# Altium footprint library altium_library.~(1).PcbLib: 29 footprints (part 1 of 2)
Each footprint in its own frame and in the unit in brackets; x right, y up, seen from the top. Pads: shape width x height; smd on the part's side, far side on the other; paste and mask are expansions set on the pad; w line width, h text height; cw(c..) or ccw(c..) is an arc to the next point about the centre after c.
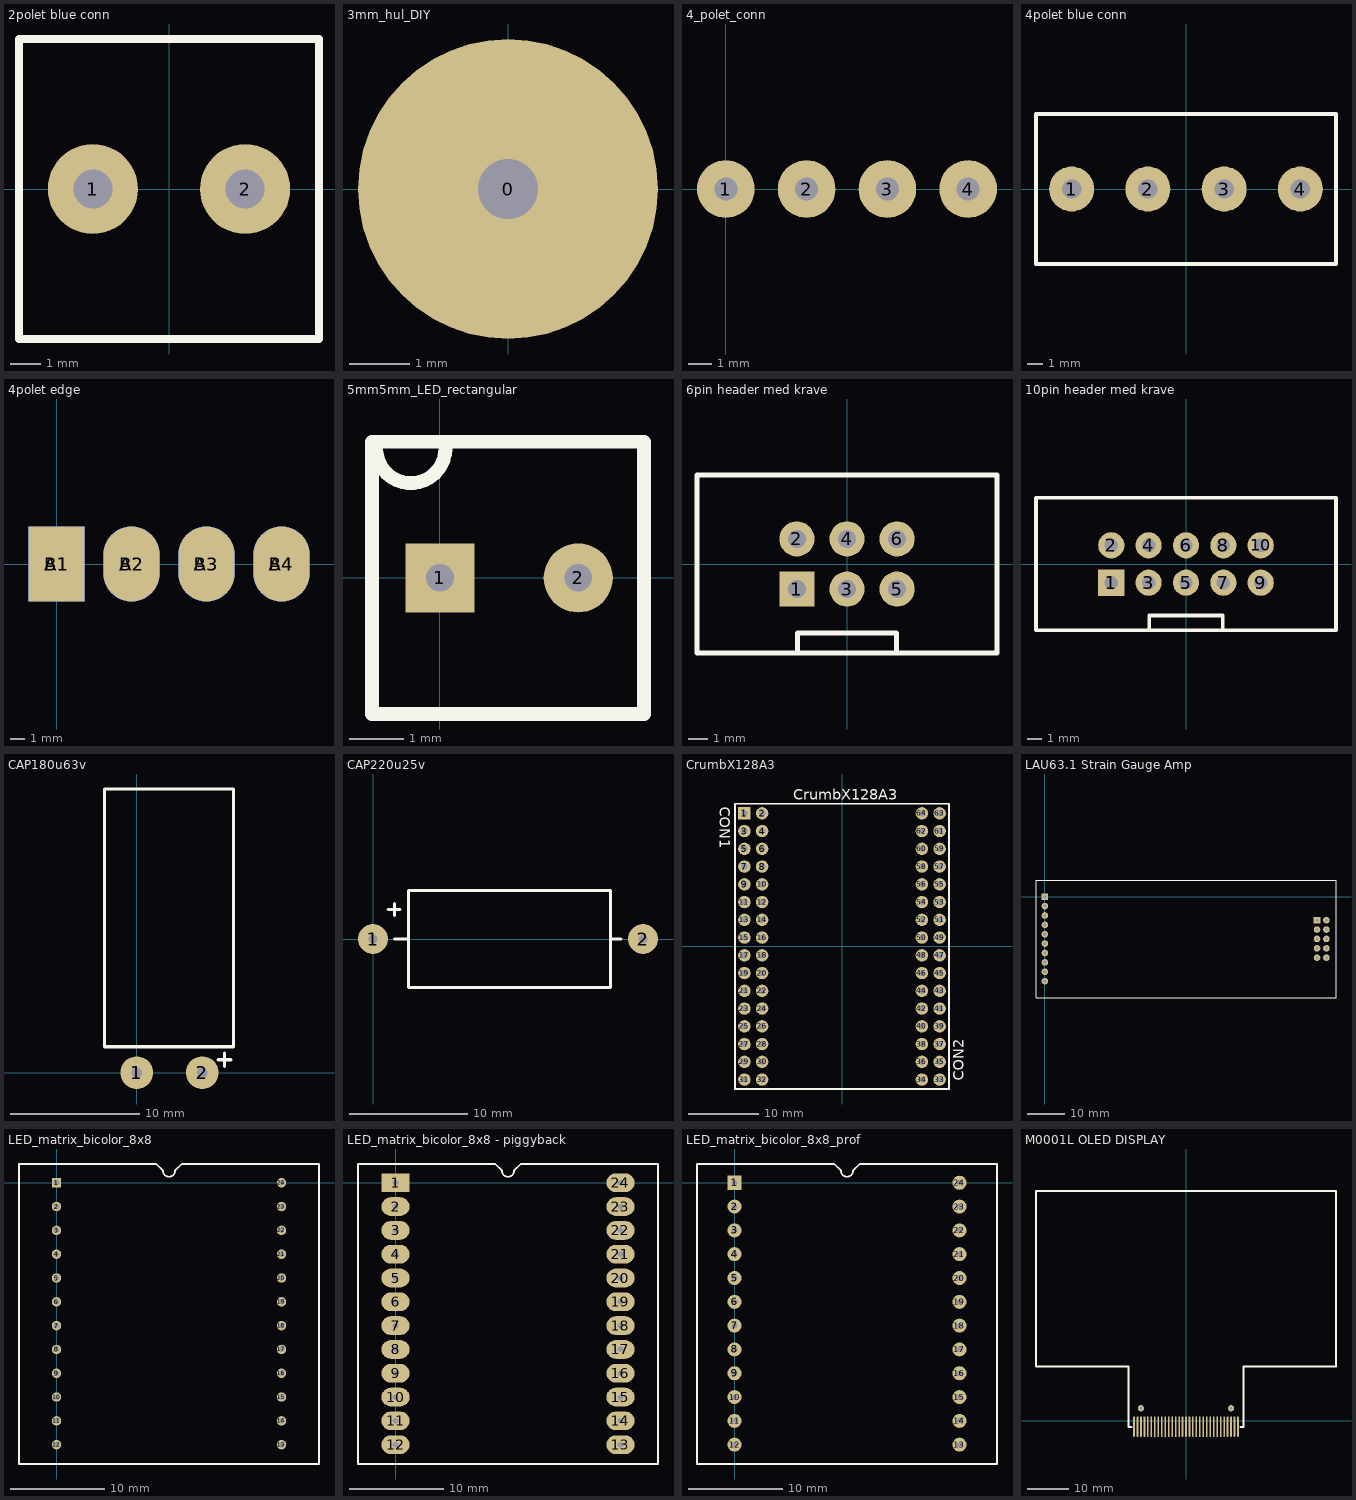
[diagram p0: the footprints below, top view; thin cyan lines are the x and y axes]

## 2polet blue conn [mm]
pads (2):
  round 3 hole 1.3: 1(-2.54,0) 2(2.54,0)
Top Overlay:
  lines w0.254: -5,-5 -5,5 5,5 5,-5 -5,-5

## 3mm_hul_DIY [mm]
pads (1):
  round 5 hole 1: 0(0,0)

## 4_polet_conn [mm]
pads (4):
  round 2.5 hole 1: 1(0,0) 2(3.5,0) 3(7,0) 4(10.5,0)

## 4polet blue conn [mm]
pads (4):
  round 3 hole 1.3: 1(-7.62,0) 2(-2.54,0) 3(2.54,0) 4(7.62,0)
Top Overlay:
  lines w0.254: -10,-5 -10,5 10,5 10,-5 -10,-5

## 4polet edge [mil]
pads (8):
  rect 150x200 smd: A1(0,0)
  oval 150x200 smd: A2(200,0) A3(400,0) A4(600,0)
  rect 150x200 smd far side: B1(0,0)
  oval 150x200 smd far side: B2(200,0) B3(400,0) B4(600,0)

## 5mm5mm_LED_rectangular [mil]
pads (2):
  rect 50x50 hole 20: 1(0,0)
  round 50 hole 20: 2(100,0)
Top Overlay:
  lines w10: -46.06,93.5 ccw(c-21.06,93.5) 3.94,93.5 ; 25,98.43 147.64,98.43 147.64,-98.43 -49.21,-98.43 -49.21,98.43 75,98.43

## 6pin header med krave [mil]
pads (6):
  rect 70x70 hole 35.43: 1(-100,-50)
  round 70 hole 35.43: 2(-100,50) 3(0,-50) 4(0,50) 5(100,-50) 6(100,50)
Top Overlay:
  lines w10: -98.43,-173.23 -98.43,-137.8 98.43,-137.8 98.43,-173.23 ; -299.21,-177.17 299.21,-177.17 299.21,177.17 -299.21,177.17 -299.21,-177.17

## 10pin header med krave [mil]
pads (10):
  rect 70x70 hole 35.43: 1(-200,-50)
  round 70 hole 35.43: 2(-200,50) 3(-100,-50) 4(-100,50) 5(0,-50) 6(0,50) 7(100,-50) 8(100,50) 9(200,-50) 10(200,50)
Top Overlay:
  lines w10: -98.43,-173.23 -98.43,-137.8 98.43,-137.8 98.43,-173.23 ; -401.57,-177.17 401.57,-177.17 401.57,177.17 -401.57,177.17 -401.57,-177.17

## CAP180u63v [mm]
pads (2):
  round 2.54 hole 0.8: 1(0,0) 2(5.08,0)
Top Overlay:
  lines w0.254: 6.3,1 7.316,1 ; 6.81,0.492 6.81,1.508 ; -2.5,2 -2.5,22 7.5,22 7.5,2 -2.5,2

## CAP220u25v [mm]
pads (2):
  round 2.54 hole 0.8: 1(0,0) 2(22.86,0)
Top Overlay:
  lines w0.254: 1.284,2.5 2.3,2.5 ; 1.8,0 3,0 3,4.1 20.1,4.1 20.1,-4.1 3,-4.1 3,-1.045 3,0.3 ; 1.8,2 1.8,3.016 ; 20.1,0 21,0

## CrumbX128A3 [mil]
pads (64):
  rect 70x70 hole 35.43: 1(-550,750)
  round 70 hole 35.43: 2(-450,750) 3(-550,650) 4(-450,650) 5(-550,550) 6(-450,550) 7(-550,450) 8(-450,450) 9(-550,350) 10(-450,350) 11(-550,250) 12(-450,250) 13(-550,150) 14(-450,150) 15(-550,50) 16(-450,50) 17(-550,-50.12) 18(-450,-50.12) 19(-550,-150) 20(-450,-150) 21(-550,-250) 22(-450,-250) 23(-550,-350) 24(-450,-350) 25(-550,-450) 26(-450,-450) 27(-550,-550) 28(-450,-550) 29(-550,-650) 30(-450,-650) 31(-550,-750) 32(-450,-750) 33(550,-750) 34(450,-750) 35(550,-650) 36(450,-650) 37(550,-550) 38(450,-550) 39(550,-450) 40(450,-450) 41(550,-350) 42(450,-350) 43(550,-250) 44(450,-250) 45(550,-150) 46(450,-150) 47(550,-50.12) 48(450,-50.12) 49(550,50) 50(450,50) 51(550,150) 52(450,150) 53(550,250) 54(450,250) 55(550,350) 56(450,350) 57(550,450) 58(450,450) 59(550,550) 60(450,550) 61(550,650) 62(450,650) 63(550,750) 64(450,750)
Top Overlay:
  lines w10: -602.36,-803.15 602.36,-803.15 602.36,803.15 -602.36,803.15 -602.36,-803.15
  text "CrumbX128A3" at -275.59,826.77 h60
  text "." at 633.86,-787.4 h60
  text "CON2" at 685.04,-755.91 h60
  text "CON1" at -688.98,787.4 h60

## LAU63.1 Strain Gauge Amp [mil]
pads (20):
  rect 70x70 hole 35: 0(0,0) 10(2900,-250)
  round 70 hole 35: 1(0,-100) 2(0,-200) 3(0,-300) 4(0,-400) 5(0,-500) 6(0,-600) 7(0,-700) 8(0,-800) 9(0,-900) 11(3000,-250) 12(2900,-350) 13(3000,-350) 14(2900,-450) 15(3000,-450) 16(2900,-550) 17(3000,-550) 18(2900,-650) 19(3000,-650)
Top Overlay:
  lines w10: -94.49,-1078.74 3102.36,-1078.74 3102.36,177.17 1345.28,177.17 -94.49,177.17 -94.49,-1078.74

## LED_matrix_bicolor_8x8 [mm]
pads (24):
  rect 1x1 / inner rect 3x2 / far side rect 3x2 hole 0.6: 1(0,0)
  round 1 / inner oval 3x2 / far side oval 3x2 hole 0.6: 2(0,-2.54) 3(0,-5.08) 4(0,-7.62) 5(0,-10.16) 6(0,-12.7) 7(0,-15.24) 8(0,-17.78) 9(0,-20.32) 10(0,-22.86) 11(0,-25.4) 12(0,-27.94) 13(24,-27.94) 14(24,-25.4) 15(24,-22.86) 16(24,-20.32) 17(24,-17.78) 18(24,-15.24) 19(24,-12.7) 20(24,-10.16) 21(24,-7.62) 22(24,-5.08) 23(24,-2.54) 24(24,0)
Top Overlay:
  lines w0.2: -4,-30 28,-30 28,2 13.365,2 12.635,1.27 cw(c12,1.27) 11.365,1.27 10.635,2 -4,2 -4,-30

## LED_matrix_bicolor_8x8 - piggyback [mm]
pads (24):
  rect 3x2 hole 0.6: 1(0,0)
  oval 3x2 hole 0.6: 2(0,-2.54) 3(0,-5.08) 4(0,-7.62) 5(0,-10.16) 6(0,-12.7) 7(0,-15.24) 8(0,-17.78) 9(0,-20.32) 10(0,-22.86) 11(0,-25.4) 12(0,-27.94) 13(24,-27.94) 14(24,-25.4) 15(24,-22.86) 16(24,-20.32) 17(24,-17.78) 18(24,-15.24) 19(24,-12.7) 20(24,-10.16) 21(24,-7.62) 22(24,-5.08) 23(24,-2.54) 24(24,0)
Top Overlay:
  lines w0.2: -4,-30 28,-30 28,2 13.365,2 12.635,1.27 cw(c12,1.27) 11.365,1.27 10.635,2 -4,2 -4,-30

## LED_matrix_bicolor_8x8_prof [mm] "made for proffesional pcb manuf."
height 8
pads (24):
  rect 1.5x1.5 hole 0.6: 1(0,0)
  round 1.5 hole 0.6: 2(0,-2.54) 3(0,-5.08) 4(0,-7.62) 5(0,-10.16) 6(0,-12.7) 7(0,-15.24) 8(0,-17.78) 9(0,-20.32) 10(0,-22.86) 11(0,-25.4) 12(0,-27.94) 13(24,-27.94) 14(24,-25.4) 15(24,-22.86) 16(24,-20.32) 17(24,-17.78) 18(24,-15.24) 19(24,-12.7) 20(24,-10.16) 21(24,-7.62) 22(24,-5.08) 23(24,-2.54) 24(24,0)
Top Overlay:
  lines w0.2: -4,-30 28,-30 28,2 13.365,2 12.635,1.27 cw(c12,1.27) 11.365,1.27 10.635,2 -4,2 -4,-30

## M0001L OLED DISPLAY [mm]
pads (33):
  oval 0.4x5 smd: 1(-12.675,-1.5) 2(-11.83,-1.5) 3(-10.985,-1.5) 4(-10.14,-1.5) 5(-9.295,-1.5) 6(-8.45,-1.5) 7(-7.605,-1.5) 8(-6.76,-1.5) 9(-5.915,-1.5) 10(-5.07,-1.5) 11(-4.225,-1.5) 12(-3.38,-1.5) 13(-2.535,-1.5) 14(-1.69,-1.5) 15(-0.845,-1.5) 16(0,-1.5) 17(0.845,-1.5) 18(1.69,-1.5) 19(2.535,-1.5) 20(3.38,-1.5) 21(4.225,-1.5) 22(5.07,-1.5) 23(5.915,-1.5) 24(6.76,-1.5) 25(7.605,-1.5) 26(8.45,-1.5) 27(9.295,-1.5) 28(10.14,-1.5) 29(10.985,-1.5) 30(11.83,-1.5) 31(12.675,-1.5)
  round 1.524 hole 0.762: 40(-11,3) 41(11,3)
Top Overlay:
  lines w0.508: -13.3,-1.6 -14,-1.6 -14,13.2 -36.6,13.2 -36.6,56 36.6,56 36.6,13.2 14,13.2 14,-1.6 13.3,-1.6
